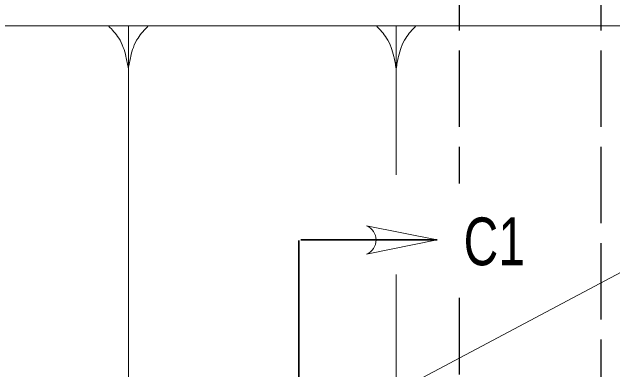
# Model space of a CAD drawing. Extents: x 1043.1 to 1101.1, y 672.4 to 716.4.
# Drawn here: x 1052.643 to 1055.663, y 710.169 to 711.966 of the extents above; entities that cross this region are included whole.
import ezdxf
from ezdxf.enums import TextEntityAlignment as Align

# ---------------------------------------------------------------- set-up
doc = ezdxf.new("R2010")
doc.units = 0
doc.header["$LTSCALE"] = 0.064
doc.linetypes.add('LONG_DASHED', pattern=[7.5, 6, -1.5])
doc.layers.add('1', color=7, linetype='Continuous', lineweight=13)

msp = doc.modelspace()

# ---------------------------------------------------------------- linework, layer by layer
at = {"layer": '1', "linetype": 'LONG_DASHED', "lineweight": 25}
for p, q in [((1054.88983, 713.71008), (1054.88983, 711.10542)), ((1055.6025, 713.71008), (1055.6025, 709.6515)), ((1054.88983, 710.5305), (1054.88983, 709.97025))]:
    msp.add_line(p, q, dxfattribs=at)
at = {"layer": '1'}
for p, q in [((1047.132, 711.89675), (1056.394, 711.89675)), ((1053.12858, 711.89675), (1053.32658, 711.89675)), ((1053.22758, 709.93942), (1053.22758, 711.89675)), ((1054.47442, 711.89675), (1054.67225, 711.89675)), ((1054.47442, 711.89675), (1054.67225, 711.89675)), ((1054.57325, 711.14967), (1054.57325, 711.89675)), ((1054.57325, 709.68142), (1054.57325, 710.64842))]:
    msp.add_line(p, q, dxfattribs=at)
at = {"layer": '1', "lineweight": 35}
for p, q in [((1054.0845, 710.52092), (1054.0845, 710.81992)), ((1054.09358, 710.822), (1054.77883, 710.822)), ((1054.0845, 709.97375), (1054.0845, 710.52092))]:
    msp.add_line(p, q, dxfattribs=at)
at = {"layer": '1'}
for points in [[(1054.42483, 710.89283), (1054.77883, 710.822), (1054.42483, 710.75125), (1054.42492, 710.75133)], [(1054.27542, 709.90208), (1055.89358, 710.76142), (1056.61417, 710.76142)]]:
    msp.add_lwpolyline(points, dxfattribs=at)
msp.add_arc((1054.39621, 710.82211), 0.0764, 292.08605, 67.91218, dxfattribs=at)
for points in [[(1053.22758, 711.68092), (1053.21567, 711.74358), (1053.20225, 711.78875), (1053.17892, 711.836), (1053.12858, 711.89675)], [(1053.32658, 711.89675), (1053.27608, 711.836), (1053.25267, 711.78875), (1053.23942, 711.74358), (1053.22758, 711.68092)], [(1054.57325, 711.68092), (1054.56142, 711.74358), (1054.54792, 711.78875), (1054.52467, 711.836), (1054.47442, 711.89675)], [(1054.57325, 711.68092), (1054.56142, 711.74358), (1054.54792, 711.78875), (1054.52467, 711.836), (1054.47442, 711.89675)], [(1054.67225, 711.89675), (1054.62183, 711.836), (1054.5985, 711.78875), (1054.58517, 711.74358), (1054.57325, 711.68092)], [(1054.67225, 711.89675), (1054.62183, 711.836), (1054.5985, 711.78875), (1054.58517, 711.74358), (1054.57325, 711.68092)]]:
    msp.add_spline(points, degree=3, dxfattribs=at)

# ---------------------------------------------------------------- texts
at = {"layer": '1', "width": 0.75}
msp.add_text('C1', height=0.24, dxfattribs=at).set_placement((1055.06633, 710.69475), align=Align.CENTER)

doc.saveas('drawing.dxf')
